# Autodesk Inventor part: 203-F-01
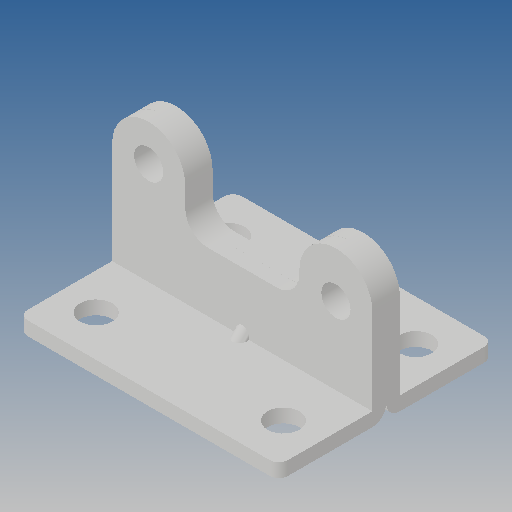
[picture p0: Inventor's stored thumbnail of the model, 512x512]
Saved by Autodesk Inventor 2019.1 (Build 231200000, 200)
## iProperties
Created: 2011-05
Part Number: 203-F-01
Material: Ogólny
Document SubType Name: Modeling
Designer: CADENGINEERING4
Density: 1 g/cm^3
Appearance: Domyślna
Author: CADENGINEERING4
Revision Number: ÈÎºÎ
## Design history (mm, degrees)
feature "µ¹½Ç2"
feature "¾µÏò4"
node "Bryła1"
node "Bryła2"
